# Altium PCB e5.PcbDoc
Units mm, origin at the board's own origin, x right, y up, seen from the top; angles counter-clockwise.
Board outline 100 x 60 mm, 2 copper layers (Top Layer, Bottom Layer), stack 0.325 mm thick; 69 components, 138 nets, 392 pads, 130 vias.
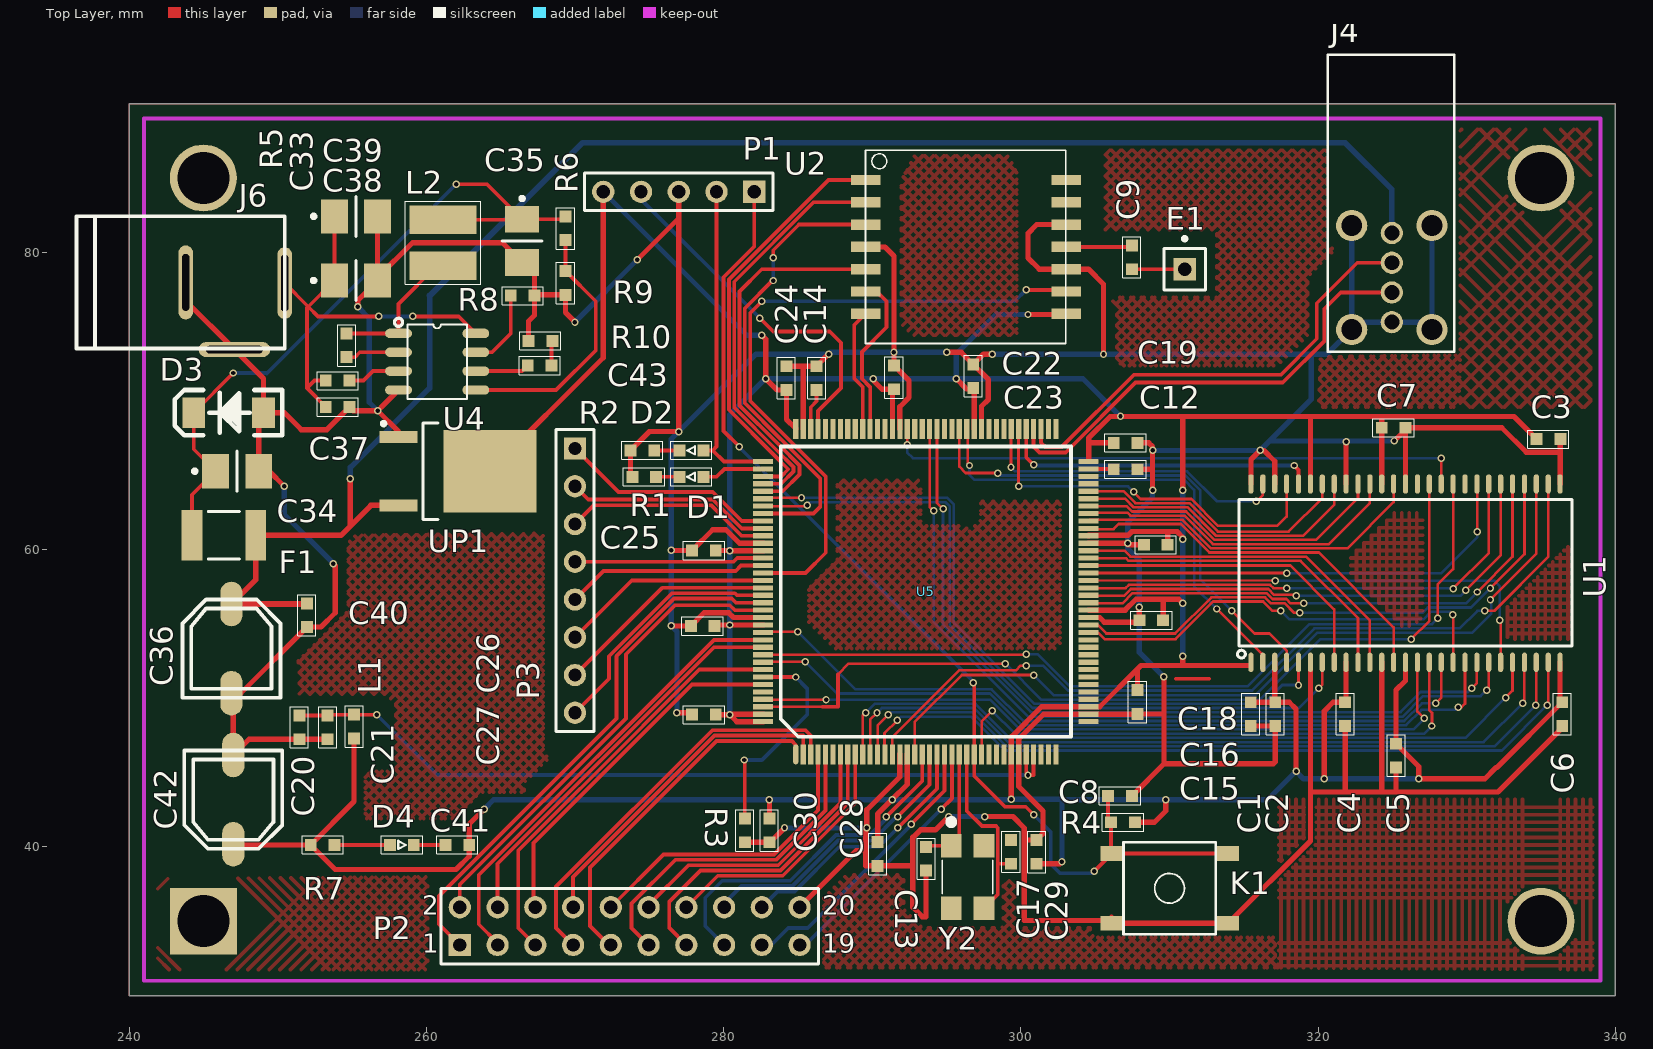
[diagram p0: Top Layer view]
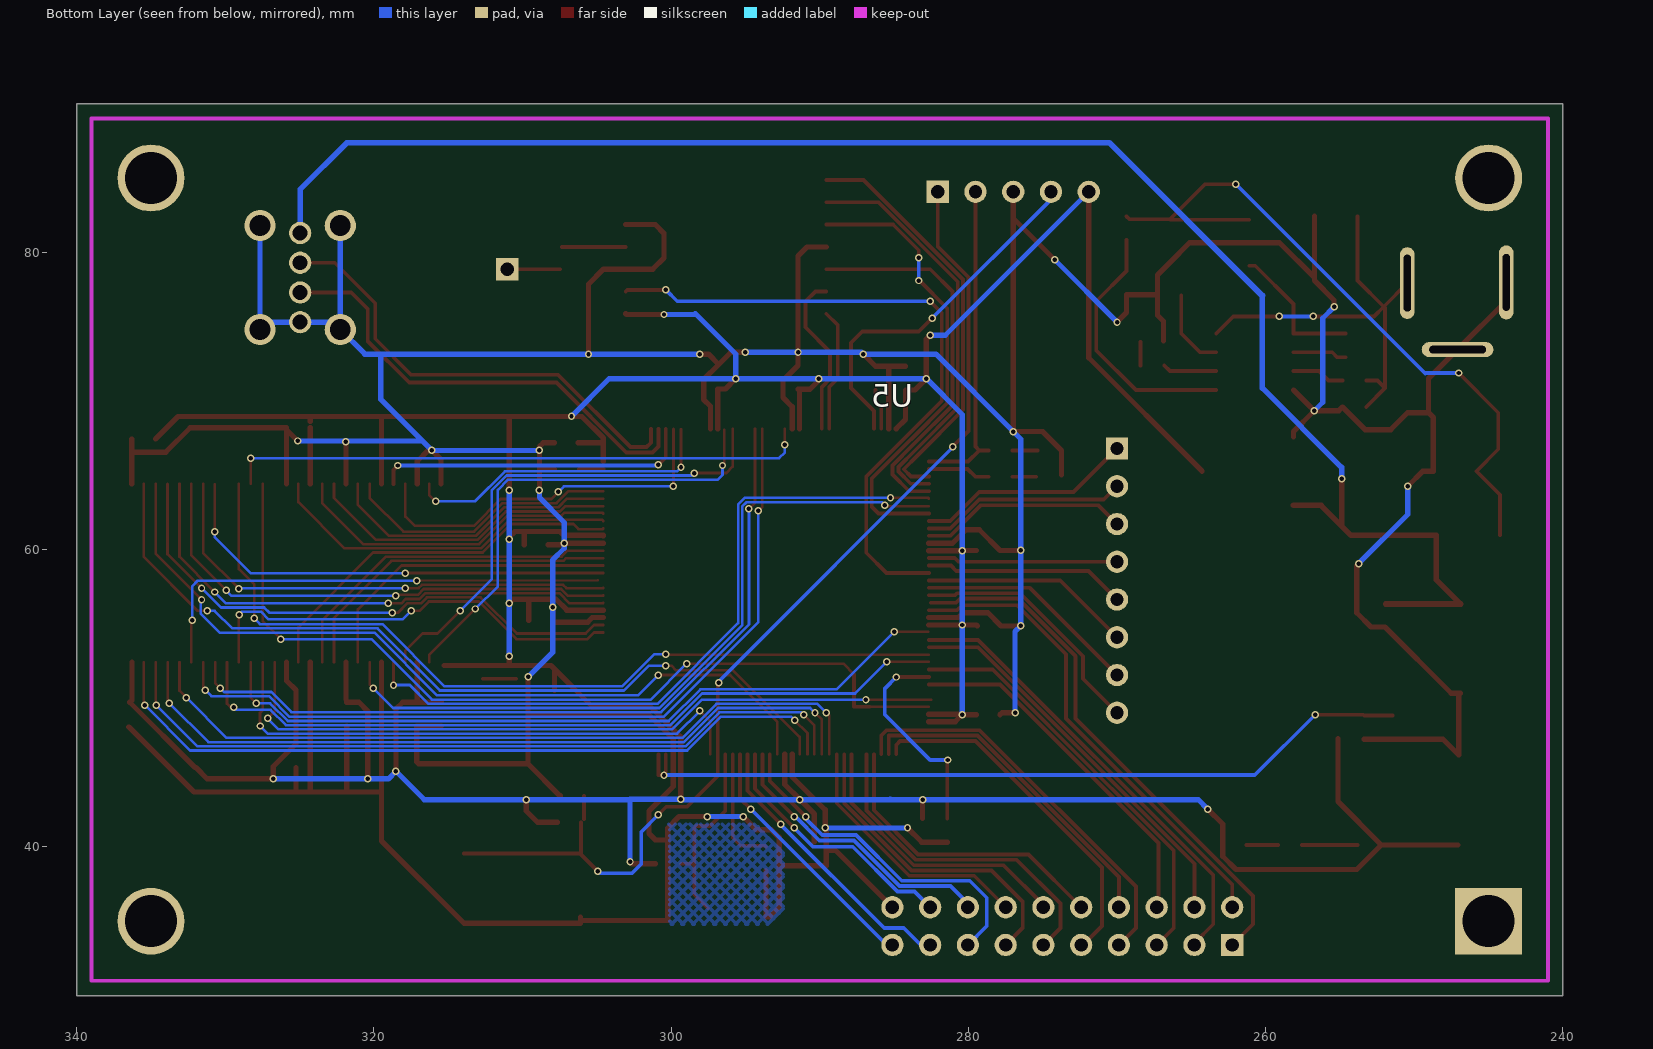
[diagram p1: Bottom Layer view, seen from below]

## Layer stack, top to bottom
Top Solder: solder mask 0.0102, Solder Resist, Dk 3.5
Top Layer: signal copper 0.0356
Dielectric 1: core 0.254, FR-4, Dk 4.2
Bottom Layer: signal copper 0.0356
Bottom Solder: solder mask 0.0102, Solder Resist, Dk 3.5

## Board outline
240,30 240,90 340,90 340,30

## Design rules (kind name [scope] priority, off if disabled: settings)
Clearance GND [All] p1: gap=0.104
HoleSize [All] p1: absolutevalues=TRUE maxlimit=4.5 minlimit=0.3 maxpercent=80.000 minpercent=20.000
HoleToHoleClearance [All] p1: gap=0.1 allowstackedmicrovias=TRUE
MinimumSolderMaskSliver [All] p1: minsoldermaskwidth=0.01
PolygonConnect PolygonConnect_1 [All vs IsNamedPolygon('GND_L01_P000')] p1: connectstyle=Relief reliefconductorwidth=0.254 reliefentries=4 polygonreliefangle="90 Angle" airgapwidth=0.254
PolygonConnect [IsVia] p2: connectstyle=Direct reliefconductorwidth=0.254 reliefentries=4 polygonreliefangle="90 Angle" airgapwidth=0.254
RoomDefinition Sheet1 [InComponentClass('Sheet1')] p1: confinementstyle=ConfineIn formatcopy=TRUE lockcomponents=FALSE outline 235.077,0 337.185,0 337.185,91.44 235.077,91.44
RoutingVias [All] p1: holewidth=0.3 width=0.5 viastyle="Through Hole" minholewidth=0.1 minwidth=0.3 maxholewidth=0.6 maxwidth=1
SilkToSilkClearance [All] p1: silktosilkclearance=0.01
SilkToSolderMaskClearance [IsPad] p1: minsilkscreentomaskgap=0 clearancetoexposedcopper=FALSE
SolderMaskExpansion [All] p1: expansion=0.102
Width Width_5V [InNet('5V')] p1: maxlimit=0.4 minlimit=0.376 preferedwidth=0.376
Width Width_SDIO [InNetClass('SDIO')] p2: maxlimit=0.254 minlimit=0.254 preferedwidth=0.254
Width Width_SDRAM [InNetClass('SDRAM')] p3: maxlimit=0.254 minlimit=0.153 preferedwidth=0.177
Width Width_GND [InNet('GND')] p4: maxlimit=0.454 minlimit=0.254 preferedwidth=0.354
Width Width_3.3V [InNet('3.3V')] p5: maxlimit=0.354 minlimit=0.254 preferedwidth=0.354
25 further rules are at their usual default settings.

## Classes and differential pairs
polygon class PolygonClass_1: GND_L01_P000

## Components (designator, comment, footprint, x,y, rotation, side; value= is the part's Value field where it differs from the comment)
C1 "C_0.1UF_0603" C_0603 315.468,48.133 r90 top
C2 "C_0.1UF_0603" C_0603 317.119,48.133 r90 top
C3 "C_0.1UF_0603" C_0603 336.296,67.437 r180 top
C4 "C_0.1UF_0603" C_0603 321.818,48.133 r90 top
C5 "C_0.1UF_0603" C_0603 325.247,45.339 r90 top
C6 "C_0.1UF_0603" C_0603 336.423,48.133 r90 top
C7 "C_0.1UF_0603" C_0603 325.882,68.199 r180 top
C8 "C_0.1UF_0603" C_0603 307.467,43.434 r180 top
C9 "CAP_NP" R_0603 307.467,78.867 r90 top
C12 "C_2.2UF_0603" CAP_0603_FIRE 307.848,65.405 r180 top
C13 "C_22P_0603" C_0603 293.624,40.005 r270 top
C14 "C_2.2UF_0603" CAP_0603_FIRE 286.258,70.739 r90 top
C15 "C_0.1UF_0603" C_0603 307.848,50.546 r270 top
C16 "C_0.1UF_0603" C_0603 307.975,55.245 r0 top
C17 "C_22P_0603" C_0603 299.339,38.862 r90 top
C18 "C_0.1UF_0603" C_0603 309.88,60.325 r180 top
C19 "C_0.1UF_0603" C_0603 307.848,67.183 r180 top
C20 "C_0.1UF_0603" C_0603 251.46,47.244 r90 top
C21 "C_0.1UF_0603" C_0603 253.365,47.244 r90 top
C22 "C_0.1UF_0603" C_0603 296.799,70.866 r90 top
C23 "C_0.1UF_0603" C_0603 291.465,72.39 r270 top
C24 "C_0.1UF_0603" C_0603 284.226,70.739 r90 top
C25 "C_0.1UF_0603" C_0603 277.876,59.944 r0 top
C26 "C_0.1UF_0603" C_0603 279.4,54.864 r180 top
C27 "C_0.1UF_0603" C_0603 277.876,48.895 r0 top
C28 "C_0.1UF_0603" C_0603 290.365,40.327 r270 top
C29 "C_0.1UF_0603" C_0603 301.066,40.462 r270 top
C30 "C_0.1UF_0603" C_0603 283.083,41.91 r270 top
C33 "C_0.1UF_0603" C_0603 254.635,74.549 r270 top
C34 "C+_10UF_B" AVX_B_3528-21 247.269,65.278 r0 top
C35 "C+_10UF_B" AVX_B_3528-21 266.446,80.772 r270 top
C36 "CAP+_47UF_6.5X6.5" EC_47UF_6.5X6.5 246.888,53.34 r0 top
C37 "C_0.1UF_0603" C_0603 253.238,69.596 r0 top
C38 "C+_10UF_B" AVX_B_3528-21 255.27,78.105 r0 top
C39 "C+_10UF_B" AVX_B_3528-21 255.27,82.423 r0 top
C40 "C_0.1UF_0603" C_0603 251.968,56.388 r270 top
C41 "C_0.1UF_0603" C_0603 262.89,40.132 r180 top
C42 "CAP+_47UF_6.5X6.5" EC_47UF_6.5X6.5 247.015,43.18 r180 top
C43 "C_2.7NF_0603" C_0603 266.827,72.39 r0 top
D1 "LED_BLUE_0603" LED_0603 278.638,64.897 r180 top
D2 "LED_RED_0603" LED_0603 278.638,66.675 r180 top
D3 "SMAJ5.0CA" DO-214 249.047,69.215 r180 top
D4 "LED_RED_0603" LED_0603 257.556,40.132 r0 top
E1 "Antenna" PIN1 311.023,78.867 r0 top
F1 "FUSE500MA" C1812 246.38,60.96 r0 top
J4 "USB-AF90" USB-AF90 327.66,74.803 r90 top
J6 "DC-005" DC-005 236.474,73.533 r0 top
K1 "KEY" SW6.2/6.2-SMD 310.007,37.211 r0 top
L1 "BEAD-0603" R_0603 255.143,48.895 r270 top
L2 "L_6.8UH_4532" GDCD4532 261.112,80.645 r90 top
P1 "Header 5" HDR1X5 282.067,84.074 r180 top
P2 "Header 10X2" HDR2X10 262.255,33.401 r0 top
P3 "Header 8" HDR1X8 270.002,66.802 r270 top
R1 "R_1K_0603" R_0603 275.463,64.897 r180 top
R2 "R_1K_0603" R_0603 275.336,66.675 r180 top
R3 "R_10K_0603" R_0603 281.432,41.91 r270 top
R4 "R_10K_0603" R_0603 306.07,41.656 r0 top
R5 "R_100K_0603" R_0603 253.238,71.374 r0 top
R6 "R_62K_0603" R_0603 269.367,82.423 r270 top
R7 "R_1K_0603" R_0603 252.222,40.132 r0 top
R8 "R_180K_0603" R_0603 265.684,77.089 r0 top
R9 "R_11.8K_0603" R_0603 269.367,78.74 r270 top
R10 "R_24K_0603" R_0603 268.478,74.041 r180 top
U1 "IS42S16400J" TSOP-54 325.882,58.42 r90 top
U2 "BL-8782" BL-8782 289.56,86.868 r0 top
U4 "RT7272" RT7272 260.731,72.644 r0 top
U5 "STM32F429_144" 429_144 284.861,46.228 r90 top
UP1 "1086-3.3" TO-252-2L 262.128,65.278 r0 top
Y2 "CRYSTAL_25MHZ" CRYSTAL_25MHZ 296.418,37.973 r270 top

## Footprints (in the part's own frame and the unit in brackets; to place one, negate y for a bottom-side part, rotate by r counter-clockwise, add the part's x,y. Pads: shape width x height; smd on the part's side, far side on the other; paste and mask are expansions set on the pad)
429_144 [mm]
  oval 1.35x0.35 smd: 1(0,0)
  rect 1.35x0.35 smd: 2(0,-0.5) 3(0,-1) 4(0,-1.5) 5(0,-2) 6(0,-2.5) 7(0,-3) 8(0,-3.5) 9(0,-4) 10(0,-4.5) 11(0,-5) 12(0,-5.5) 13(0,-6) 14(0,-6.5) 15(0,-7) 16(0,-7.5) 17(0,-8) 18(0,-8.5) 19(0,-9) 20(0,-9.5) 21(0,-10) 22(0,-10.5) 23(0,-11) 24(0,-11.5) 25(0,-12) 26(0,-12.5) 27(0,-13) 28(0,-13.5) 29(0,-14) 30(0,-14.5) 31(0,-15) 32(0,-15.5) 33(0,-16) 34(0,-16.5) 35(0,-17) 36(0,-17.5) 73(21.9,-17.5) 74(21.9,-17) 75(21.9,-16.5) 76(21.9,-16) 77(21.9,-15.5) 78(21.9,-15) 79(21.9,-14.5) 80(21.9,-14) 81(21.9,-13.5) 82(21.9,-13) 83(21.9,-12.5) 84(21.9,-12) 85(21.9,-11.5) 86(21.9,-11) 87(21.9,-10.5) 88(21.9,-10) 89(21.9,-9.5) 90(21.9,-9) 91(21.9,-8.5) 92(21.9,-8) 93(21.9,-7.5) 94(21.9,-7) 95(21.9,-6.5) 96(21.9,-6) 97(21.9,-5.5) 98(21.9,-5) 99(21.9,-4.5) 100(21.9,-4) 101(21.9,-3.5) 102(21.9,-3) 103(21.9,-2.5) 104(21.9,-2) 105(21.9,-1.5) 106(21.9,-1) 107(21.9,-0.5) 108(21.9,0)
  rect 0.35x1.35 smd: 37(2.2,-19.7) 38(2.7,-19.7) 39(3.2,-19.7) 40(3.7,-19.7) 41(4.2,-19.7) 42(4.7,-19.7) 43(5.2,-19.7) 44(5.7,-19.7) 45(6.2,-19.7) 46(6.7,-19.7) 47(7.2,-19.7) 48(7.7,-19.7) 49(8.2,-19.7) 50(8.7,-19.7) 51(9.2,-19.7) 52(9.7,-19.7) 53(10.2,-19.7) 54(10.7,-19.7) 55(11.2,-19.7) 56(11.7,-19.7) 57(12.2,-19.7) 58(12.7,-19.7) 59(13.2,-19.7) 60(13.7,-19.7) 61(14.2,-19.7) 62(14.7,-19.7) 63(15.2,-19.7) 64(15.7,-19.7) 65(16.2,-19.7) 66(16.7,-19.7) 67(17.2,-19.7) 68(17.7,-19.7) 69(18.2,-19.7) 70(18.7,-19.7) 71(19.2,-19.7) 72(19.7,-19.7) 109(19.7,2.2) 110(19.2,2.2) 111(18.7,2.2) 112(18.2,2.2) 113(17.7,2.2) 114(17.2,2.2) 115(16.7,2.2) 116(16.2,2.2) 117(15.7,2.2) 118(15.2,2.2) 119(14.7,2.2) 120(14.2,2.2) 121(13.7,2.2) 122(13.2,2.2) 123(12.7,2.2) 124(12.2,2.2) 125(11.7,2.2) 126(11.2,2.2) 127(10.7,2.2) 128(10.2,2.2) 129(9.7,2.2) 130(9.2,2.2) 131(8.7,2.2) 132(8.2,2.2) 133(7.7,2.2) 134(7.2,2.2) 135(6.7,2.2) 136(6.2,2.2) 137(5.7,2.2) 138(5.2,2.2) 139(4.7,2.2) 140(4.2,2.2) 141(3.7,2.2) 142(3.2,2.2) 143(2.7,2.2) 144(2.2,2.2)
  silkscreen extent 1.19,-18.51 20.71,1.01
AVX_B_3528-21 [mm]
  rect 1.8x2.3 smd: 1(-1.45,0) 2(1.45,0)
  silkscreen extent -2.97,-1.35 0,1.35
BL-8782 [mm]
  rect 2x0.7 smd: 1(0,-2) 2(0,-3.5) 3(0,-5) 4(0,-6.5) 5(0,-8) 6(0,-9.5) 7(0,-11) 8(13.5,-11) 9(13.5,-9.5) 10(13.5,-8) 11(13.5,-6.5) 12(13.5,-5) 13(13.5,-3.5) 14(13.5,-2)
  silkscreen extent 0,-13 13.46,0
C1812 [mm]
  rect 1.4x3.4 smd: 1(-2.15,0) 2(2.15,0)
  silkscreen extent -1.05,-1.6 1.05,1.6
C_0603 [mm]
  rect 0.8x0.8 smd: 1(0,0) 2(1.6,0)
  silkscreen extent -0.58,-0.61 2.2,0.61
CAP_0603_FIRE [mm]
  rect 0.8x0.8 smd: 1(0,0) 2(1.6,0)
  silkscreen extent -0.58,-0.61 2.2,0.61
CRYSTAL_25MHZ [mm]
  rect 1.6x1.4 smd: 1(-2.1,-1.1) 2(2.1,-1.1) 3(2.1,1.1) 4(-2.1,1.1)
  silkscreen extent -3.8,-1.7 1.13,1.7
DC-005 [mm]
  oval 1x4.826 hole 0.5 slot 3.81 at 90 deg: 1(14,4.399)
  oval 1x4.978 hole 0.5 slot 3.81 at 90 deg: 2(7.341,4.445)
  oval 4.826x1 hole 0.5 slot 3.81 at 0 deg: 3(10.617,-0.076)
  silkscreen extent 0,0 14,8.9
DO-214 [mil]
  rect 60x80 smd: 1(0,0) 2(185,0)
  silkscreen extent -50,-60 235,60
EC_47UF_6.5X6.5 [mm]
  oval 1.5x3 smd: 1(0,3) 2(0,-3)
  silkscreen extent -3.3,-3.3 3.3,3.3
GDCD4532 [mm]
  rect 1.9x4.5 smd: 1(-1.55,0) 2(1.55,0)
  silkscreen extent -2.79,-2.54 2.79,2.54
HDR1X5 [mm] "Connector; Header; 5 Position"
  rect 1.5x1.5 hole 0.9: 1(0,0)
  round 1.5 hole 0.9: 2(2.54,0) 3(5.08,0) 4(7.62,0) 5(10.16,0)
  silkscreen extent -1.27,-1.27 11.43,1.27
HDR1X8 [mm] "Connector; Header; 8 Position"
  rect 1.5x1.5 hole 0.9: 1(0,0)
  round 1.5 hole 0.9: 2(2.54,0) 3(5.08,0) 4(7.62,0) 5(10.16,0) 6(12.7,0) 7(15.24,0) 8(17.78,0)
  silkscreen extent -1.27,-1.27 19.05,1.27
HDR2X10 [mm] "Connector; Header; 10x2 Position"
  rect 1.5x1.5 hole 0.9: 1(0,0)
  round 1.5 hole 0.9: 2(0,2.54) 3(2.54,0) 4(2.54,2.54) 5(5.08,0) 6(5.08,2.54) 7(7.62,0) 8(7.62,2.54) 9(10.16,0) 10(10.16,2.54) 11(12.7,0) 12(12.7,2.54) 13(15.24,0) 14(15.24,2.54) 15(17.78,0) 16(17.78,2.54) 17(20.32,0) 18(20.32,2.54) 19(22.86,0) 20(22.86,2.54)
  silkscreen extent -1.27,-1.27 24.13,3.81
LED_0603 [mm]
  rect 0.8x0.8 smd: A(0,0) K(1.6,0)
  silkscreen extent -0.58,-0.6 2.19,0.61
PIN1 [mm] "Generic Antenna; 1 Lead"
  rect 1.5x1.5 hole 0.9: 1(0,0)
  silkscreen extent -1.4,-1.4 1.4,2.17
R_0603 [mm]
  rect 0.8x0.8 smd: 1(0,0) 2(1.6,0)
  silkscreen extent -0.58,-0.61 2.2,0.61
RT7272 [mm]
  oval 1.8x0.635 smd: 1(-2.6,1.905) 2(-2.6,0.635) 3(-2.6,-0.635) 4(-2.6,-1.905) 5(2.6,-1.905) 6(2.6,-0.635) 7(2.6,0.635) 8(2.6,1.905)
  silkscreen extent -2.87,-2.5 2,2.92
SW6.2/6.2-SMD [mm]
  rect 1.5x1 smd: 1(-3.912,2.35) 2(3.937,2.35) 3(-3.912,-2.35) 4(3.937,-2.35)
  silkscreen extent -3.1,-3.1 3.1,3.1
TO-252-2L [mm]
  rect 2.55x0.8 smd: 1(-4,2.3) 3(-4,-2.3)
  rect 6.25x5.55 smd: 2(2.15,0)
  silkscreen extent -5.12,-3.25 -1.35,3.32
TSOP-54 [mm]
  oval 1.3x0.35 smd: 1(-6,10.4) 2(-6,9.6) 3(-6,8.8) 4(-6,8) 5(-6,7.2) 6(-6,6.4) 7(-6,5.6) 8(-6,4.8) 9(-6,4) 10(-6,3.2) 11(-6,2.4) 12(-6,1.6) 13(-6,0.8) 14(-6,0) 15(-6,-0.8) 16(-6,-1.6) 17(-6,-2.4) 18(-6,-3.2) 19(-6,-4) 20(-6,-4.8) 21(-6,-5.6) 22(-6,-6.4) 23(-6,-7.2) 24(-6,-8) 25(-6,-8.8) 26(-6,-9.6) 27(-6,-10.4) 28(6,-10.4) 29(6,-9.6) 30(6,-8.8) 31(6,-8) 32(6,-7.2) 33(6,-6.4) 34(6,-5.6) 35(6,-4.8) 36(6,-4) 37(6,-3.2) 38(6,-2.4) 39(6,-1.6) 40(6,-0.8) 41(6,0) 42(6,0.8) 43(6,1.6) 44(6,2.4) 45(6,3.2) 46(6,4) 47(6,4.8) 48(6,5.6) 49(6,6.4) 50(6,7.2) 51(6,8) 52(6,8.8) 53(6,9.6) 54(6,10.4)
  silkscreen extent -5.71,-11.2 4.96,11.3
USB-AF90 [mm]
  rrect100% 1.5x1.5 hole 1: 1(6.5,2.7) 2(4.5,2.7) 3(2.5,2.7) 4(0.5,2.7)
  rrect100% 2.1x2.1 hole 1.4: 5(0,0) 6(7,0) 7(7,5.4) 8(0,5.4)
  silkscreen extent -1.5,-1.5 18.5,7

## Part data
C9: "0603, X7R, 50V, 10%(K)"
D3: "SMAJ5.0CA-E3/61 400W 5V"
E1: "Generic Antenna"
F1: "FUSE500ma"
P1: "Header, 5-Pin"
P2: "Header, 10-Pin, Dual row"
P3: "Header, 8-Pin"

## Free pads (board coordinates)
  round 4.5 hole 3.5: 0(245,85) 3(335,85)
  rect 4.5x4.5 hole 3.5: 1(245,35)
  rrect100% 4.5x4.5 hole 3.5: 2(335,35)

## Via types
v1: diameter 0.5, hole 0.3, Top Layer to Bottom Layer, 130 vias

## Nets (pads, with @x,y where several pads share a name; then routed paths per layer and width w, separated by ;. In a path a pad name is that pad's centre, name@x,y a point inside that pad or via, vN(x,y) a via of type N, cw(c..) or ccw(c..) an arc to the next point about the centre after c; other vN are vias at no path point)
3.3V: C1.2 C2.2 C3.2 C4.2 C5.2 C6.2 C7.2 C15.1 C16.2 C18.1 C19.2 C22.1 C23.2 C24.1 C25.2 C26.1 C27.2 C28.1 C29.2 C30.1 C41.1 C42.1 L1.2 P1.5 R4.2 R7.1 U1.1 U1.3 U1.9 U1.14 U1.27 U1.43 U1.49 U2.8 U5.16 U5.30 U5.39 U5.52 U5.62 U5.72 U5.84 U5.95 U5.108 U5.121 U5.131 U5.143 U5.144 UP1.2 | length 374.7
  Top Layer w0.354: C42.1@247.063,40.132 R7.1 ; L1.2 255.143,43.053 R7.1 ; v1(263.906,42.545) 262.89,41.529 C41.1 262.89,39.37 262.001,38.481 253.873,38.481 R7.1 ; UP1.2 271.907,72.907 P1.5 ; C26.1 279.464,54.928 U5.131 ; C27.2 v1(280.416,48.895) ; C25.2 280.4,59.944 v1(280.416,59.928) U5.121 ; v1(282.575,74.422) 282.829,74.168 v1(282.829,71.501) 283.591,70.739 C24.1 284.226,68.763 U5.108 ; U5.144 280.883,48.428 v1(280.416,48.895) ; U5.143 280.449,48.928 v1(280.416,48.895) ; C30.1 v1(283.083,43.18) ; v1(290.068,71.501) 290.068,71.374 290.652,70.79 C23.2 291.361,70.686 U5.95 ; C28.1 290.365,42.207 v1(291.338,43.18) 292.361,44.203 U5.16 ; v1(295.656,71.501) 296.353,70.804 296.861,70.804 U5.84 ; v1(299.361,43.202) U5.30 299.361,47.406 301.383,49.428 U5.39 305.308,49.428 307.848,51.968 ; v1(300.482,75.819) 303.011,75.819 U2.8 ; C29.2 302.641,38.862 v1(302.768,38.989) ; U5.52 307.018,55.928 307.755,56.665 310.619,56.665 v1(310.896,56.388) ; U5.62 304.561,60.959 307.212,60.959 307.467,61.214 309.88,61.214 ; U5.72 304.561,67.183 ; C19.2 304.561,67.183 ; R4.2 308.991,41.656 309.753,42.418 v1(309.753,43.18) ; C15.1 307.848,51.968 ; C16.2 309.575,56.614 ; C18.1 309.88,61.214 ; 310.896,52.324 v1(310.896,52.832) ; v1@310.896,60.833 310.515,61.214 309.88,61.214 ; v1(310.896,64.008) 310.896,68.961 ; 315.259,52.197 308.077,52.197 307.848,51.968 ; C1.2 C2.2 318.059,49.733 318.516,49.276 v1(318.516,45.085) ; C2.2@317.082,49.77 U1.3 ; 319.405,68.961 v1(306.705,68.961) 306.012,68.961 304.561,67.51 304.561,67.183 ; U1.49 319.482,68.961 324.282,68.961 ; v1(320.421,44.577) 320.421,49.149 321.005,49.733 C4.2 ; C4.2@321.882,49.923 U1.9 ; U1.43 C7.2 ; 324.282,68.631 324.282,68.961 ; U1.14 325.882,51.181 325.247,50.546 C5.2 326.771,45.415 v1(326.771,44.577) 331.216,44.577 331.978,45.339 332.029,45.339 C6.2 ; C3.2 333.172,68.961 324.282,68.961 ; C6.2@336.282,49.874 U1.27
  Bottom Layer w0.354: v1(263.906,42.545) 264.541,43.18 v1(283.083,43.18) 285.242,43.18 285.264,43.202 285.286,43.18 v1(291.338,43.18) 299.339,43.18 v1(299.361,43.202) ; P1.5 281.559,74.422 v1(282.575,74.422) ; v1(280.416,48.895) v1(280.416,54.928) v1(280.416,59.928) 280.416,69.088 v1(282.829,71.501) v1(290.068,71.501) v1(295.656,71.501) ; v1@299.361,43.18 299.384,43.203 302.745,43.203 302.768,43.18 ; v1(300.482,75.819) 298.421,75.819 298.372,75.868 295.656,73.152 v1(295.656,71.501) ; v1(302.768,38.989) 302.768,43.18 ; v1(306.705,68.961) 304.165,71.501 v1(295.656,71.501) ; v1(310.896,52.832) v1(310.896,56.388) v1(310.896,60.706) v1(310.896,64.008) ; v1(326.771,44.577) v1(320.421,44.577) 319.024,44.577 v1(318.516,45.085) 316.611,43.18 v1(309.753,43.18) 302.768,43.18
5V: C36.1 C40.1 F1.2 J4.1 UP1.3 | length 111.7
  Top Layer w0.376: C40.1@251.92,56.34 C36.1 248.53,57.982 F1.2 254.254,60.96 254.889,61.595 ; v1(254.889,64.77) 254.889,61.595 ; UP1.3 256.272,62.978 254.889,61.595
  Bottom Layer w0.376: v1(254.889,64.77) 254.889,65.532 260.223,70.866 260.223,77.089 ; 318.897,87.376 321.818,87.376 324.96,84.234 J4.1
  Bottom Layer w0.4: 260.223,77.089 270.51,87.376 318.897,87.376
GND: C1.1 C2.1 C3.1 C4.1 C5.1 C6.1 C7.1 C8.1 C12.1 C13.2 C14.2 C15.2 C16.1 C17.2 C18.2 C19.1 C20.1 C21.1 C22.2 C23.1 C24.2 C25.1 C26.2 C27.1 C28.2 C29.1 C30.2 C34.2 C35.2 C36.2 C37.2 C38.2 C39.2 C40.2 C42.2 D3.1 J4.4 J4.5 J4.6 J4.7 J4.8 J6.2 J6.3 K1.3 K1.4 P1.3 P2.20 pad.0 pad.1 pad.2 pad.3 R1.2 R2.2 R3.2 R8.2 R9.2 R10.2 U1.6 U1.12 U1.28 U1.41 U1.46 U1.52 U1.54 U2.4 U2.10 U2.12 U4.4 U5.15 U5.31 U5.38 U5.51 U5.61 U5.83 U5.94 U5.107 U5.120 U5.130 UP1.1 | length 506.7
  Top Layer w0.354: J6.2 243.815,76.733 J6.3 249.047,71.501 D3.1 ; v1(250.444,64.262) 249.428,65.278 C34.2 248.719,68.887 D3.1 ; C21.1 C20.1 248.079,47.244 C42.2 247.015,50.213 C36.2 247.52,50.34 C40.2 252.908,54.788 253.873,55.753 253.873,58.928 v1(253.746,59.055) ; v1(255.397,76.327) 255.397,76.782 C38.2 C38.2@256.72,78.3 ; C39.2 C38.2@256.72,78.3 ; 256.955,69.562 U4.4 ; UP1.1 258.128,67.948 v1(256.734,69.342) 255.092,69.342 C37.2 253.314,68.072 251.587,68.072 250.444,69.215 D3.1 ; R10.2 266.878,75.362 267.284,75.768 R8.2 ; v1(270.002,75.311) 269.367,75.946 R9.2 267.335,77.14 R8.2 ; R1.2@273.736,65.024 R2.2 275.006,67.945 v1(276.987,67.945) 276.987,82.296 ; v1(274.193,79.502) 276.987,82.296 ; v1(276.479,54.864) C26.2 278.689,55.753 280.342,55.753 280.667,55.428 U5.130 ; v1(276.479,59.944) C25.1 279.273,61.341 280.162,61.341 281.075,60.428 U5.120 ; v1(276.86,49.022) 277.749,49.022 C27.1 ; P1.3 276.987,82.296 ; R3.2 C30.2 283.134,40.31 v1(284.099,41.275) ; C24.2 C14.2 v1(287.071,73.152) ; P2.20 288.925,39.751 289.568,39.751 ; U5.107 285.361,72.331 ; U2.4 290.853,80.368 291.465,79.756 v1(291.465,73.279) C23.1 292.481,71.374 292.481,70.231 291.861,69.611 U5.94 ; U5.15 291.861,44.719 289.635,42.493 v1(289.635,41.275) 289.568,41.208 289.568,39.751 ; C13.2 293.624,35.306 293.37,35.306 292.735,35.941 292.735,38.727 ; v1(295.021,73.279) 295.986,73.279 C22.2 ; v1(295.148,42.037) 294.259,41.148 293.243,41.148 292.735,40.64 292.735,38.727 ; U5.83 297.361,69.65 297.815,70.104 297.815,71.45 C22.2 ; v1(297.561,42.037) 299.466,42.037 300.228,41.275 300.228,40.513 ; v1(298.069,73.152) 297.485,73.152 C22.2 ; U2.12 301.07,81.868 300.482,81.28 300.482,79.629 301.243,78.868 U2.10 304.545,78.868 305.562,77.851 v1(305.562,73.152) ; U5.51 305.308,55.428 305.618,55.118 307.848,55.118 C16.1 v1(307.975,56.134) ; U5.61 v1(307.189,60.428) 307.189,60.325 C18.2 ; K1.3@305.904,35.052 300.228,35.052 300.228,40.513 ; K1.3@306.095,35.281 K1.3 K1.4 319.482,40.399 319.482,43.688 ; C8.1 309.626,45.593 ; C15.2@307.83,48.928 U5.38 301.531,48.928 299.861,47.258 U5.31 299.861,44.055 301.498,42.418 301.498,40.894 C29.1 300.279,40.462 300.228,40.513 ; C15.2 309.55,48.946 ; C12.1 308.864,65.405 ; C19.1 308.61,67.183 308.864,66.929 v1(308.864,66.675) 308.864,65.405 ; v1(308.864,64.008) 308.864,65.405 ; v1(309.626,51.435) 309.626,45.593 ; C1.1 C2.1 317.119,45.72 316.992,45.593 309.626,45.593 ; U1.54 315.482,66.054 v1(316.103,66.675) 316.357,66.675 317.082,65.95 U1.52 ; U1.6 319.482,43.688 ; C4.1 321.818,43.688 ; U1.46 v1(321.882,67.246) ; U1.12 324.282,43.688 ; v1(325.12,67.31) C7.1@326.009,68.199 ; C5.1 325.247,43.688 ; U1.41 C7.1 C7.1@326.009,68.199 ; U1.28 336.296,64.434 336.296,66.548 ; C3.1 336.296,66.548 ; C6.1@336.486,48.069 332.105,43.688 325.247,43.688 ; C38.2@256.72,78.3 259.065,80.645 265.123,80.645 C35.2 267.284,78.484 R8.2 ; 289.568,39.751 289.568,38.727 C28.2 292.735,38.727 ; 319.482,43.688 321.818,43.688 ; 321.818,43.688 324.282,43.688 ; 324.282,43.688 325.247,43.688 ; C7.1@326.009,68.199 332.359,68.199 334.01,66.548 336.296,66.548
  Bottom Layer w0.354: v1(250.444,64.262) 250.444,62.357 v1(253.746,59.055) ; v1(255.397,76.327) 256.159,75.565 256.159,69.917 v1(256.734,69.342) ; v1(270.002,75.311) v1(274.193,79.502) ; v1(276.86,49.022) 276.86,54.483 v1(276.479,54.864) v1(276.479,59.944) 276.479,67.437 v1(276.987,67.945) 282.194,73.152 v1(287.071,73.152) 287.198,73.279 v1(291.465,73.279) v1(295.021,73.279) ; v1(284.099,41.275) v1(289.635,41.275) ; v1(295.148,42.037) v1(297.561,42.037) ; v1(298.069,73.152) v1(305.562,73.152) 319.532,73.152 ; v1(308.864,64.008) 308.864,63.5 307.189,61.825 v1(307.189,60.428) 307.189,60.095 307.975,59.309 v1(307.975,56.134) 307.975,53.086 v1(309.626,51.435) ; v1(308.864,66.675) v1(316.103,66.675) 316.738,67.31 ; J4.7 J4.8 ; v1(325.12,67.31) 316.738,67.31 ; J4.6 J4.5 327.16,75.303 J4.4 322.76,75.303 J4.8 ; 316.738,67.31 319.532,70.104 319.532,73.152 ; 319.532,73.152 320.609,73.152 J4.8
NetC8_2: C8.2 K1.1 K1.2 P1.1 R4.1 U5.25 | length 72.5
  Top Layer w0.254: v1(281.051,66.929) 280,67.98 280,78.324 282.067,80.391 P1.1 ; v1(296.799,51.054) 296.861,50.992 U5.25 296.861,44.769 298.931,42.699 300.328,42.699 v1(300.863,42.164) ; v1(304.927,38.354) K1.1@306.07,39.497 ; R4.1@305.867,41.859 C8.2 ; R4.1 K1.1@306.07,39.497 ; K1.2 306.134,39.561 K1.1@306.07,39.497
  Bottom Layer w0.254: v1(281.051,66.929) 281.051,66.884 296.799,51.136 v1(296.799,51.054) ; v1(300.863,42.164) 302.006,41.021 302.006,38.862 302.641,38.227 304.8,38.227 v1(304.927,38.354)
NetC9_1: C9.1 E1.1 | length 3.6
  Top Layer w0.254: C9.1 E1.1
NetC9_2: C9.2 U2.11 | length 4.3
  Top Layer w0.254: U2.11 C9.2@307.368,80.368
NetC12_2: C12.2 U5.71 | length 1.7
  Top Layer w0.254: U5.71 C12.2@306.225,65.428
NetC13_1: C13.1 U5.23 Y2.1 | length 8.1
  Top Layer w0.254: C13.1 293.692,40.073 Y2.1 295.861,40.616 U5.23
NetC14_1: C14.1 U5.106 | length 2.8
  Top Layer w0.254: U5.106 285.861,69.58 286.258,69.977 C14.1
NetC17_1: C17.1 U5.24 Y2.3 | length 13
  Top Layer w0.254: U5.24 296.361,42.419 297.378,41.402 298.323,41.402 298.45,41.275 298.45,38.862 ; Y2.3 298.45,36.805 298.45,38.862 ; C17.1 298.45,38.862
NetC20_2: C20.2 C21.2 L1.1 U5.32 U5.33 | length 54
  Top Layer w0.254: C20.2 C21.2 ; C21.2@253.441,48.895 L1.1 v1(256.667,48.895) ; U5.32 300.361,44.833 300.363,44.831 v1(300.482,44.831) ; v1@300.363,44.833 300.861,44.833 U5.33
  Bottom Layer w0.254: v1(256.667,48.895) 260.731,44.831 296.799,44.831 v1(300.482,44.831)
NetC33_1: C33.1 L2.1 U4.1 | length 9.5
  Top Layer w0.254: C33.1 U4.1 258.131,76.521 260.705,79.095 L2.1
NetC33_2: C33.2 U4.2 | length 3.6
  Top Layer w0.254: C33.2 255.194,72.949 255.524,73.279 U4.2
NetC34_1: C34.1 C35.1 D3.2 F1.1 L2.2 R6.1 | length 47.3
  Top Layer w0.254: F1.1 244.23,63.689 C34.1 244.348,66.749 D3.2 v1(247.015,71.882) ; L2.2 266.419,82.195 C35.1 ; v1(262.001,84.582) 264.086,84.582 C35.1 ; R6.1 269.166,82.222 C35.1
  Bottom Layer w0.254: v1(247.015,71.882) 249.226,71.882 249.263,71.844 v1(262.001,84.582)
NetC37_1: C37.1 C38.1 C39.1 J6.1 R5.1 U4.8 | length 29.9
  Top Layer w0.254: J6.1 252.061,76.346 ; C37.1 251.968,70.866 ; R5.1 252.476,71.374 251.968,70.866 ; C39.1 C38.1 252.061,76.346 ; v1(256.794,75.692) 252.714,75.692 252.061,76.346 ; v1(259.08,75.692) 262.188,75.692 U4.8 ; 251.968,70.866 251.968,76.253 252.061,76.346
  Bottom Layer w0.254: v1(256.794,75.692) v1(259.08,75.692)
NetC41_2: C41.2 D4.K | length 2.1
  Top Layer w0.254: D4.K C41.2
NetC43_1: C43.1 U4.6 | length 3.7
  Top Layer w0.254: U4.6 266.446,72.009 C43.1
NetC43_2: C43.2 R10.1 | length 1.6
  Top Layer w0.254: C43.2 R10.1@268.427,73.99
NetD1_A: D1.A U5.110 | length 4.2
  Top Layer w0.254: D1.A 279.527,64.897 280.058,65.428 U5.110
NetD1_K: D1.K R1.1 | length 1.6
  Top Layer w0.254: R1.1 D1.K
NetD2_A: D2.A P1.2 U5.109 | length 21.8
  Top Layer w0.254: D2.A 279.273,66.675 ; P1.2 279.527,66.929 279.273,66.675 ; U5.109 280.02,65.928 279.273,66.675
NetD2_K: D2.K R2.1 | length 1.7
  Top Layer w0.254: R2.1 D2.K
NetD4_A: D4.A R7.2 | length 3.7
  Top Layer w0.254: R7.2 D4.A
NetJ4_2: J4.2 U5.75 | length 31.2
  Top Layer w0.254: U5.75 301.361,67.193 301.654,66.9 302.739,66.9 307.608,71.769 317.5,71.769 319.913,74.182 319.913,76.581 322.635,79.303 J4.2
NetJ4_3: J4.3 U5.76 | length 31.2
  Top Layer w0.254: U5.76 300.861,66.931 301.25,66.542 303.016,66.542 307.721,71.247 317.627,71.247 320.421,74.041 320.421,76.2 321.524,77.303 J4.3
NetP1_4: P1.4 U5.105 | length 24.4
  Top Layer w0.254: v1(282.448,75.565) 283.337,74.676 287.147,74.676 287.909,73.914 287.909,70.866 286.361,69.318 U5.105
  Bottom Layer w0.254: P1.4 274.447,83.566 v1(282.448,75.565)
NetP2_1: P2.1 U5.128 | length 36.4
  Top Layer w0.254: P2.1 260.858,34.798 260.858,36.703 272.796,48.641 272.796,52.834 276.674,56.712 280.556,56.712 280.84,56.428 U5.128@282.534,56.428
NetP2_2: P2.2 U5.129 | length 32.4
  Top Layer w0.254: P2.2 262.255,37.465 273.43,48.64 273.43,52.962 276.73,56.261 280.416,56.261 280.749,55.928 U5.129
NetP2_3: P2.3 U5.133 | length 30.9
  Top Layer w0.254: P2.3 264.795,33.528 263.525,34.798 263.525,38.1 279.353,53.928 U5.133
NetP2_4: P2.4 U5.134 | length 26.7
  Top Layer w0.254: P2.4@265.049,36.195 264.795,36.449 264.795,38.864 279.359,53.428 U5.134
NetP2_5: P2.5 U5.137 | length 28.3
  Top Layer w0.254: P2.5 266.192,34.544 266.192,39.749 274.597,48.154 274.597,48.159 278.366,51.928 U5.137
NetP2_6: P2.6 U5.139 | length 24.2
  Top Layer w0.254: P2.6 267.208,36.068 267.208,40.259 277.877,50.928 U5.139
NetP2_7: P2.7 U5.3 | length 27.3
  Top Layer w0.254: P2.7 268.732,34.544 268.732,37.335 279.245,47.848 285.509,47.848 285.843,47.514 285.861,47.514 U5.3
NetP2_8: P2.8 U5.2 | length 22.7
  Top Layer w0.254: P2.8 269.875,37.971 279.394,47.49 285.361,47.49 U5.2
NetP2_9: P2.9 U5.1 | length 24
  Top Layer w0.254: P2.9 272.288,33.401 271.018,34.671 271.018,38.608 279.527,47.117 284.607,47.117 284.861,46.863 U5.1
NetP2_10: P2.10 U5.4 | length 20.4
  Top Layer w0.254: P2.10 275.96,39.486 283.386,39.486 286.361,42.461 U5.4
NetP2_11: P2.11 U5.5 | length 22.7
  Top Layer w0.254: P2.11 273.812,34.544 273.812,36.195 276.745,39.128 283.534,39.128 286.861,42.455 U5.5
NetP2_12: P2.12 U5.7 | length 19.2
  Top Layer w0.254: P2.12 274.955,36.091 277.634,38.77 283.682,38.77 287.861,42.949 U5.7
NetP2_13: P2.13 U5.8 | length 21.4
  Top Layer w0.254: P2.13 276.352,34.544 276.352,36.322 278.442,38.412 283.831,38.412 288.361,42.942 U5.8
NetP2_14: P2.14 U5.9 | length 17.6
  Top Layer w0.254: P2.14 279.608,38.054 283.979,38.054 288.861,42.936 U5.9
NetP2_15: P2.15 U5.18 | length 23.4
  Top Layer w0.254: v1(290.957,42.037) 293.361,44.441 U5.18
  Bottom Layer w0.254: P2.15 278.765,34.671 278.765,36.576 279.908,37.719 284.48,37.719 287.555,40.794 289.834,40.794 290.957,41.917 v1(290.957,42.037)
NetP2_16: P2.16 U5.19 | length 19.4
  Top Layer w0.254: v1(291.719,42.037) 293.861,44.179 U5.19
  Bottom Layer w0.254: P2.16 280.035,36.195 281.201,37.361 284.628,37.361 287.703,40.436 290.036,40.436 291.637,42.037 v1(291.719,42.037)
NetP2_17: P2.17 U5.21 | length 19.2
  Top Layer w0.254: P2.17@282.448,33.401 P2.17 ; v1(292.635,41.511) 292.635,41.556 294.861,43.782 U5.21
  Bottom Layer w0.254: P2.17 283.21,33.401 284.353,34.544 285.668,34.544 v1(292.635,41.511)
NetP2_18: P2.18 U5.20 | length 17.4
  Top Layer w0.254: v1(291.719,41.275) 294.361,43.917 U5.20
  Bottom Layer w0.254: P2.18 283.637,37.003 284.777,37.003 287.779,40.005 290.449,40.005 v1(291.719,41.275)
NetP2_19: P2.19 U5.22 | length 17.3
  Top Layer w0.254: v1(294.64,42.545) 295.361,43.266 U5.22
  Bottom Layer w0.254: P2.19 285.496,33.401 v1(294.64,42.545)
NetP3_1: P3.1 U5.117 | length 14.7
  Top Layer w0.254: P3.1 272.923,63.881 279.273,63.881 281.226,61.928 U5.117
NetP3_2: P3.2 U5.118 | length 13.8
  Top Layer w0.254: P3.2 270.891,63.373 279.275,63.373 281.22,61.428 U5.118
NetP3_3: P3.3 U5.119 | length 14
  Top Layer w0.254: P3.3 271.272,62.992 279.146,62.992 281.21,60.928 U5.119
NetP3_4: P3.4 U5.122 | length 12.8
  Top Layer w0.254: P3.4 280.67,59.182 280.916,59.428 U5.122
NetP3_5: P3.5 U5.123 | length 13.6
  Top Layer w0.254: P3.5 271.93,58.57 280.82,58.57 281.178,58.928 U5.123
NetP3_6: P3.6 U5.125 | length 14.2
  Top Layer w0.254: P3.6 273.828,57.928 U5.125
NetP3_7: P3.7 U5.126 | length 15.1
  Top Layer w0.254: P3.7 275.868,57.428 U5.126
NetP3_8: P3.8 U5.127 | length 16.9
  Top Layer w0.254: P3.8 272.288,51.308 272.288,52.832 276.526,57.07 280.759,57.07 280.901,56.928 U5.127
NetR3_1: R3.1 U5.138 | length 14.5
  Top Layer w0.254: v1(281.397,45.847) 281.432,45.812 R3.1 ; U5.138 v1(284.861,51.428)
  Bottom Layer w0.254: v1(281.397,45.847) 282.575,45.847 285.623,48.895 285.623,50.666 v1(284.861,51.428)
NetR5_2: R5.2 U4.3 | length 3.6
  Top Layer w0.254: R5.2 255.778,71.374 256.413,72.009 U4.3
NetR6_2: R6.2 R9.1 U4.5 | length 17.4
  Top Layer w0.254: U4.5 268.732,70.739 271.399,73.406 271.399,76.708 R9.1 R6.2
NetR8_1: R8.1 U4.7 | length 5.4
  Top Layer w0.254: U4.7 264.414,73.279 265.684,74.549 R8.1
NetU1_2: U1.2 U5.85 | length 32.1
  Top Layer w0.177: U5.85@296.418,68.071 296.418,65.786 v1(296.545,65.659) ; v1(313.182,56.007) 316.282,52.907 U1.2
  Bottom Layer w0.177: v1(296.545,65.659) 296.545,65.024 296.864,64.705 310.961,64.705 311.658,64.008 311.658,57.531 v1(313.182,56.007)
NetU1_4: U1.4 U5.86 | length 34
  Top Layer w0.177: U5.86 295.861,65.581 296.291,65.151 v1(298.45,65.151) ; v1(314.198,55.88) 315.722,54.356 316.726,54.356 317.882,53.2 U1.4
  Bottom Layer w0.177: v1(298.45,65.151) 298.615,64.986 311.078,64.986 312.075,63.988 312.075,58.003 v1(314.198,55.88)
NetU1_5: U1.5 U5.114 | length 48.5
  Top Layer w0.177: U5.114 282.733,63.5 v1(285.242,63.5) ; v1(318.682,50.888) U1.5
  Bottom Layer w0.177: v1(285.242,63.5) 295.028,63.5 295.491,63.038 295.491,55.048 300.91,49.629 316.329,49.629 317.588,50.888 v1(318.682,50.888)
NetU1_7: U1.7 U5.115 | length 50.3
  Top Layer w0.177: U5.115 285.559,62.928 v1(285.623,62.992) ; v1(320.04,50.673) 320.282,50.915 U1.7
  Bottom Layer w0.177: v1(285.623,62.992) 285.818,63.187 294.944,63.187 295.21,62.921 295.21,54.932 300.793,49.348 318.715,49.348 v1(320.04,50.673)
NetU1_8: U1.8 U5.58 | length 21.3
  Top Layer w0.177: U5.58 318.135,58.928 321.082,55.981 U1.8
NetU1_10: U1.10 U5.59 | length 22.8
  Top Layer w0.177: U5.59 307.078,59.428 307.259,59.247 318.832,59.247 322.682,55.397 U1.10
NetU1_11: U1.11 U5.60 | length 23.7
  Top Layer w0.177: U5.60 306.975,59.928 307.375,59.528 319.186,59.528 323.482,55.232 U1.11
NetU1_13: U1.13 U5.63 | length 25.9
  Top Layer w0.177: U5.63 304.617,61.371 306.237,61.371 306.587,61.722 310.769,61.722 312.682,59.809 320.048,59.809 325.082,54.775 U1.13
NetU1_15: U1.15 U5.141 | length 49.7
  Top Layer w0.177: U5.141@282.517,49.911 v1(286.893,49.911) ; U1.15 326.682,49.111 v1(327.152,48.641)
  Bottom Layer w0.177: v1(286.893,49.911) 297.933,49.911 299.939,47.904 326.415,47.904 v1(327.152,48.641)
NetU1_16: U1.16 U5.26 | length 38
  Top Layer w0.177: U5.26 297.361,48.441 v1(298.069,49.149) ; U1.16 327.471,52.41 327.471,49.211 327.66,49.022 v1(327.66,48.133)
  Bottom Layer w0.177: v1(298.069,49.149) 299.595,47.623 327.15,47.623 v1(327.66,48.133)
NetU1_17: U1.17 U5.132 | length 51.1
  Top Layer w0.177: U5.132@282.716,54.483 v1(284.988,54.483) ; v1(327.914,49.657) 328.282,50.025 U1.17
  Bottom Layer w0.177: v1(284.988,54.483) 288.87,50.601 298.038,50.601 300.172,48.466 325.795,48.466 326.985,49.657 v1(327.914,49.657)
NetU1_18: U1.18 U5.49 | length 29.7
  Top Layer w0.177: U5.49 305.183,54.428 305.636,53.975 310.404,53.975 312.936,56.507 316.309,56.507 316.936,55.88 v1(317.5,55.88) ; v1(329.057,55.626) 329.082,55.601 U1.18
  Bottom Layer w0.177: v1(317.5,55.88) 318.07,55.31 327.09,55.31 327.606,55.826 328.857,55.826 v1(329.057,55.626)
NetU1_19: U1.19 U5.136 | length 52.3
  Top Layer w0.177: U5.136@282.684,52.451 v1(285.496,52.451) ; v1(329.438,49.403) 329.646,49.403 329.882,49.639 U1.19
  Bottom Layer w0.177: v1(285.496,52.451) 287.627,50.32 297.921,50.32 300.056,48.185 325.911,48.185 326.94,49.214 329.249,49.214 v1(329.438,49.403)
NetU1_20: U1.20 U5.89 | length 53.9
  Top Layer w0.177: U5.89 294.361,63.144 v1(294.767,62.738) ; v1(330.327,50.673) 330.682,51.028 U1.20
  Bottom Layer w0.177: v1(294.767,62.738) 294.767,54.977 300.677,49.067 325.546,49.067 326.898,50.419 330.073,50.419 v1(330.327,50.673)
NetU1_21: U1.21 U5.90 | length 55.6
  Top Layer w0.177: U5.90 293.861,62.882 v1(294.132,62.611) ; v1(331.343,50.546) 331.482,50.685 U1.21
  Bottom Layer w0.177: v1(294.132,62.611) 294.132,55.118 300.503,48.747 325.678,48.747 327.069,50.138 330.935,50.138 v1(331.343,50.546)
NetU1_22: U1.22 U5.56 | length 32.5
  Top Layer w0.177: U5.56@304.942,57.928 v1(317.119,57.912) ; U1.22 v1@332.282,55.195
  Bottom Layer w0.177: v1(317.119,57.912) 331.851,57.912 332.232,57.531 v1(332.232,55.245)
NetU1_23: U1.23 U5.10 | length 50.7
  Top Layer w0.177: U5.10 289.361,48.823 v1(289.56,49.022) ; v1(332.613,50.038) 333.082,50.507 U1.23
  Bottom Layer w0.177: v1@289.623,49.085 290.167,49.629 296.963,49.629 299.25,47.342 329.917,47.342 v1(332.613,50.038)
NetU1_24: U1.24 U5.11 | length 51.4
  Top Layer w0.177: U5.11 289.861,48.561 v1(290.322,49.022) ; v1(333.756,49.657) 333.882,49.783 U1.24
  Bottom Layer w0.177: v1(290.322,49.022) 290.648,49.348 296.847,49.348 299.151,47.044 331.143,47.044 v1(333.756,49.657)
NetU1_25: U1.25 U5.12 | length 51.6
  Top Layer w0.177: U5.12 290.361,48.172 v1(291.084,48.895) ; v1(334.645,49.53) 334.682,49.567 U1.25
  Bottom Layer w0.177: v1(291.084,48.895) 291.238,49.049 296.748,49.049 299.034,46.763 331.878,46.763 v1(334.645,49.53)
NetU1_26: U1.26 U5.13 | length 51.6
  Top Layer w0.177: U5.13@290.83,46.228 290.83,47.652 v1(291.692,48.514) ; v1(335.407,49.53) 335.482,49.605 U1.26
  Bottom Layer w0.177: v1(291.692,48.514) 291.946,48.768 296.632,48.768 298.918,46.482 332.359,46.482 v1(335.407,49.53)
NetU1_29: U1.29 U5.14 | length 56.6
  Top Layer w0.177: U5.14 291.361,47.394 295.848,51.881 299.662,51.881 299.978,52.197 v1(300.355,52.197) ; v1(331.216,55.88) 331.851,55.88 335.482,59.511 U1.29
  Bottom Layer w0.177: v1(300.355,52.197) 301.498,52.197 303.176,50.519 315.568,50.519 319.748,54.699 329.527,54.699 330.708,55.88 v1(331.216,55.88)
NetU1_30: U1.30 U5.17 | length 55.1
  Top Layer w0.177: U5.17 292.861,48.386 296.037,51.562 v1(300.863,51.562) ; v1(331.597,56.642) 334.682,59.727 U1.30
  Bottom Layer w0.177: v1(300.863,51.562) 302.234,50.191 315.748,50.191 319.975,54.418 330.379,54.418 331.659,55.697 331.659,56.58 v1(331.597,56.642)
NetU1_31: U1.31 U5.50 | length 37.4
  Top Layer w0.177: U5.50 305.183,54.928 305.755,54.356 310.388,54.356 312.82,56.788 316.425,56.788 316.814,56.399 317.743,56.399 318.389,55.753 v1(318.77,55.753) ; v1(331.597,57.404) 331.974,57.781 333.883,59.69 U1.31
  Bottom Layer w0.177: v1(318.77,55.753) 327.025,55.753 327.379,56.107 330.291,56.107 331.588,57.404 v1(331.597,57.404)
NetU1_32: U1.32 U5.53 | length 35.3
  Top Layer w0.177: U5.53 304.601,56.388 306.832,56.388 307.513,57.069 316.542,57.069 316.93,56.68 317.859,56.68 318.151,56.388 v1(319.024,56.388) ; v1(330.708,57.15) 333.082,59.524 U1.32
  Bottom Layer w0.177: v1(319.024,56.388) 329.946,56.388 v1(330.708,57.15)
NetU1_33: U1.33 U5.54 | length 34
  Top Layer w0.177: U5.54 304.593,56.896 306.943,56.896 307.396,57.35 316.658,57.35 317.046,56.961 318.451,56.961 v1(318.516,56.896) ; v1(329.946,57.277) 332.282,59.613 U1.33
  Bottom Layer w0.177: v1(318.516,56.896) 329.565,56.896 v1(329.946,57.277)
NetU1_34: U1.34 U5.55 | length 32.8
  Top Layer w0.177: U5.55 304.585,57.404 307.053,57.404 307.28,57.631 316.774,57.631 317.001,57.404 v1(317.881,57.404) ; v1(329.089,57.372) 331.482,59.765 U1.34
  Bottom Layer w0.177: v1(317.881,57.404) 329.057,57.404 v1(329.089,57.372)
NetU1_35: U1.35 U5.57 | length 30.7
  Top Layer w0.177: U5.57 317.873,58.428 v1(317.881,58.42) ; v1(330.708,61.214) U1.35@330.708,64.389
  Bottom Layer w0.177: v1(317.881,58.42) 328.295,58.42 330.708,60.833 v1(330.708,61.214)
NetU1_37: U1.37 U5.135 | length 57.6
  Top Layer w0.177: U5.135 v1@300.355,52.928 ; v1(328.041,55.372) 328.041,57.658 329.082,58.699 U1.37
  Bottom Layer w0.177: v1@300.381,52.954 301.139,52.954 303.292,50.8 315.247,50.8 319.438,54.991 327.66,54.991 v1(328.041,55.372)
  other v1: 300.355,52.959
NetU1_38: U1.38 U5.93 | length 39.4
  Top Layer w0.177: v1(292.354,67.056) U5.93@292.354,68.121 ; U1.38 v1(328.282,66.154)
  Bottom Layer w0.177: v1(292.354,67.056) 292.354,66.535 292.735,66.154 v1(328.282,66.154)
NetU1_39: U1.39 U5.142 | length 59.7
  Top Layer w0.177: U5.142 286.639,49.428 ; 287.693,51.6 288.417,52.324 v1(298.958,52.324) ; v1(326.263,53.975) 327.482,55.194 U1.39
  Top Layer w0.254: 286.639,49.428 287.68,49.428 287.693,49.441 287.693,51.6
  Bottom Layer w0.177: v1(298.958,52.324) 301.372,49.91 316.102,49.91 320.167,53.975 v1(326.263,53.975)
NetU1_42: U1.42 U5.64 | length 23.8
  Top Layer w0.177: U5.64 304.636,62.003 310.885,62.003 312.798,60.09 321.964,60.09 325.082,63.208 U1.42
NetU1_44: U1.44 U5.65 | length 22.3
  Top Layer w0.177: U5.65 304.617,62.484 307.164,62.484 307.364,62.284 311.002,62.284 312.915,60.371 320.721,60.371 323.482,63.132 U1.44
NetU1_45: U1.45 U5.66 | length 21.2
  Top Layer w0.177: U5.66 307.117,62.928 307.48,62.565 311.118,62.565 313.031,60.652 319.859,60.652 322.682,63.475 U1.45
NetU1_47: U1.47 U5.67 | length 19.8
  Top Layer w0.177: U5.67 307.015,63.428 307.597,62.846 311.235,62.846 313.148,60.933 318.997,60.933 321.082,63.018 U1.47
NetU1_48: U1.48 U5.68 | length 18.7
  Top Layer w0.177: U5.68 306.912,63.928 307.713,63.127 311.351,63.127 313.264,61.214 318.008,61.214 320.282,63.488 U1.48
NetU1_50: U1.50 U5.77 | length 21.5
  Top Layer w0.254: U5.77 300.361,66.208 v1(300.857,65.711) ; v1(318.389,65.659) 318.682,65.366 U1.50
  Bottom Layer w0.254: v1(300.857,65.711) 300.91,65.659 v1(318.389,65.659)
NetU1_51: U1.51 U5.78 | length 25.4
  Top Layer w0.177: v1(299.847,64.262) U5.78@299.847,68.114 ; v1(307.594,63.881) 308.067,63.408 311.303,63.408 311.467,63.408 313.28,61.595 317.246,61.595 317.882,62.231 U1.51
  Bottom Layer w0.177: v1(299.847,64.262) 307.213,64.262 v1(307.594,63.881)
NetU1_53: U1.53 U5.79 | length 21.4
  Top Layer w0.177: v1(299.339,65.532) U5.79@299.339,68.106 ; v1(315.849,63.246) 316.282,63.679 U1.53
  Bottom Layer w0.177: v1(299.339,65.532) 299.604,65.267 311.194,65.267 313.215,63.246 v1(315.849,63.246)
NetU2_1: U2.1 U5.111 | length 28.3
  Top Layer w0.254: U5.111 283.868,64.928 284.353,65.413 283.432,66.334 283.429,66.334 280.358,69.405 280.358,78.176 287.05,84.868 U2.1
NetU2_2: U2.2 U5.112 | length 27.9
  Top Layer w0.254: U5.112 283.884,64.428 284.711,65.255 284.711,65.561 283.58,66.692 283.577,66.692 280.716,69.553 280.716,78.027 286.057,83.368 U2.2
NetU2_3: U2.3 U5.116 | length 31.2
  Top Layer w0.254: U5.116 286.048,62.428 286.512,62.892 286.512,64.773 283.877,67.408 283.874,67.408 281.432,69.85 281.432,76.245 283.292,78.105 v1(283.337,78.105) ; v1(283.337,79.629) 283.337,80.137 285.063,81.863 285.063,81.868 U2.3
  Bottom Layer w0.254: v1(283.337,78.105) v1(283.337,79.629)
NetU2_5: U2.5 U5.113 | length 26
  Top Layer w0.254: U5.113 283.984,63.928 285.115,65.059 285.115,65.663 283.728,67.05 283.726,67.05 281.074,69.702 281.074,77.373 282.569,78.868 U2.5
NetU2_6: U2.6 U5.98 | length 11.2
  Top Layer w0.254: U2.6 290.297,77.368 290.957,76.708 290.957,74.957 289.306,73.306 289.306,71.501 289.861,70.946 U5.98
NetU2_7: U2.7 U5.99 | length 8.3
  Top Layer w0.254: U5.99 289.361,70.94 288.798,71.503 288.798,75.106 U2.7
NetU2_9: U2.9 U5.124 | length 45
  Top Layer w0.254: v1(282.575,76.708) 281.79,75.923 281.79,70.001 286.87,64.921 286.87,59.794 285.504,58.428 U5.124 ; v1(300.355,77.47) 302.958,77.47 U2.9
  Bottom Layer w0.254: v1(282.575,76.708) 299.593,76.708 v1(300.355,77.47)
NetU5_6: U5.6
NetU5_27: U5.27
NetU5_28: U5.28
NetU5_29: U5.29
NetU5_34: U5.34
NetU5_35: U5.35
NetU5_36: U5.36
NetU5_37: U5.37
NetU5_40: U5.40
NetU5_41: U5.41
NetU5_42: U5.42
NetU5_43: U5.43
NetU5_44: U5.44
NetU5_45: U5.45
NetU5_46: U5.46
NetU5_47: U5.47
NetU5_48: U5.48
NetU5_69: U5.69
NetU5_70: U5.70
NetU5_73: U5.73
NetU5_74: U5.74
NetU5_80: U5.80
NetU5_81: U5.81
NetU5_82: U5.82
NetU5_87: U5.87
NetU5_88: U5.88
NetU5_91: U5.91
NetU5_92: U5.92
NetU5_96: U5.96
NetU5_97: U5.97
NetU5_100: U5.100
NetU5_101: U5.101
NetU5_102: U5.102
NetU5_103: U5.103
NetU5_104: U5.104
NetU5_140: U5.140
pads on no net: U1.36 U1.40 U2.13 U2.14 Y2.2 Y2.4
copper on no net: | length 2.2
  Top Layer w0.254: 310.433,51.308 312.674,51.308

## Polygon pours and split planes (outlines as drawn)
GND on Top Layer "GND_L01_P000" (hatched 90Degree grid 0.508 track 0.254, shelved, pour order 0): 240,30 240,90 340,90 340,30
GND on Top Layer "Top Layer-No Net" (hatched 45Degree grid 0.762 track 0.254, pour order 7): 329.565,88.265 329.565,69.596 338.328,69.596 338.328,88.265
GND on Top Layer "Top Layer-No Net" (hatched 90Degree grid 0.508 track 0.254, pour order 9): 338.455,31.75 338.455,43.18 317.5,43.18 317.246,42.926 317.373,42.799 317.373,31.877
GND on Top Layer "Top Layer-No Net" (hatched 45Degree grid 0.508 track 0.254, pour order 11): 255.27,60.96 254.762,60.452 254.762,55.88 251.333,52.451 251.46,52.324 251.46,50.292 257.302,50.292 257.937,49.657 257.937,45.085 256.286,45.085 255.905,44.704 255.905,41.91 261.874,41.91 263.652,43.688 266.573,43.688 266.573,44.323 268.224,45.974 267.843,46.355 267.843,61.087
GND on Top Layer "Top Layer-No Net" (hatched 45Degree grid 0.508 track 0.254, pour order 13): 288.036,64.643 293.116,64.643 293.243,64.516 293.243,61.595 296.164,61.595 296.545,61.214 297.307,61.976 297.307,63.246 302.514,63.246 302.641,63.119 302.641,53.34 287.528,53.34 286.639,54.229 285.75,55.118 285.75,57.023 285.75,57.404 287.528,59.182 287.655,59.309 287.655,64.643
GND on Top Layer "Top Layer-No Net" (hatched 45Degree grid 0.508 track 0.254, pour order 15): 291.973,84.836 291.973,75.184 292.481,74.676 292.735,74.422 299.72,74.422 299.72,85.344 299.212,86.36 299.085,86.487 292.862,86.487
GND on Top Layer "Top Layer-No Net" (hatched 45Degree grid 0.508 track 0.254, pour order 17): 260.096,37.973 260.096,31.877 259.969,31.75 241.935,31.75 241.935,37.846
GND on Top Layer "Top Layer-No Net" (hatched 90Degree grid 0.508 track 0.254, pour order 19): 325.247,62.484 325.12,62.484 322.199,59.563 322.199,58.293 325.628,54.864 326.39,54.864 327.025,55.499 327.025,62.484
GND on Top Layer "Top Layer-No Net" (hatched 90Degree grid 0.508 track 0.254, pour order 21): 332.74,56.134 332.74,54.102 332.867,53.975 336.931,53.975 336.931,60.325
GND on Top Layer "Top Layer-No Net" (hatched 45Degree grid 0.508 track 0.254, pour order 23): 320.167,72.962 320.04,69.723 320.167,69.596 329.438,69.596 329.565,72.962 329.565,73.089
GND on Top Layer "Top Layer-No Net" (hatched 45Degree grid 0.508 track 0.254, pour order 27): 292.1,38.1 288.29,38.1 286.893,36.703 286.766,36.576 286.766,31.877 317.246,31.877 317.373,32.004 317.119,32.258 317.119,33.909 305.181,33.909 305.054,33.782 304.673,34.163 304.673,34.544 299.974,34.544 299.847,34.417 299.593,34.671 299.593,36.449 299.593,37.719 298.831,37.719 298.831,34.671 298.704,34.544 293.751,34.544 293.37,34.544 292.1,35.814
GND on Top Layer "Top Layer-No Net" (hatched 45Degree grid 0.508 track 0.254, pour order 33): 305.816,86.868 305.689,86.741 305.689,81.534 312.928,81.534 313.182,81.28 313.182,76.962 306.451,76.962 306.197,76.708 306.451,76.454 306.451,73.533 306.451,72.771 306.832,72.39 317.119,72.39 317.246,72.39 319.405,74.549 319.278,74.676 319.278,78.105 319.278,78.359 321.056,80.137 320.548,80.645 320.548,86.868
GND on Bottom Layer "Top Layer-No Net" (hatched 45Degree grid 0.508 track 0.254, pour order 29): 294.132,41.275 292.481,39.624 292.481,35.814 292.735,35.56 293.497,34.798 300.101,34.798 300.101,41.275 300.355,41.529 294.259,41.529

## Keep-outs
Keep-Out Layer:
  lines w0.254: 241,31 339,31 339,89 241,89 241,31

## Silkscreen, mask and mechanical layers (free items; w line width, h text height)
Mechanical 1:
  the board outline again, w0.254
